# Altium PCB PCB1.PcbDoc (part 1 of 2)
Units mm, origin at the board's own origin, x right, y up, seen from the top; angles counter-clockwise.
Board outline 82.55 x 101.6 mm, 4 copper layers (Top Layer, GND, POWER, Bottom Layer), stack 1.586 mm thick; 125 components, 82 nets, 451 pads, 255 vias.
Unrouted connection lines stored in the file: 4.
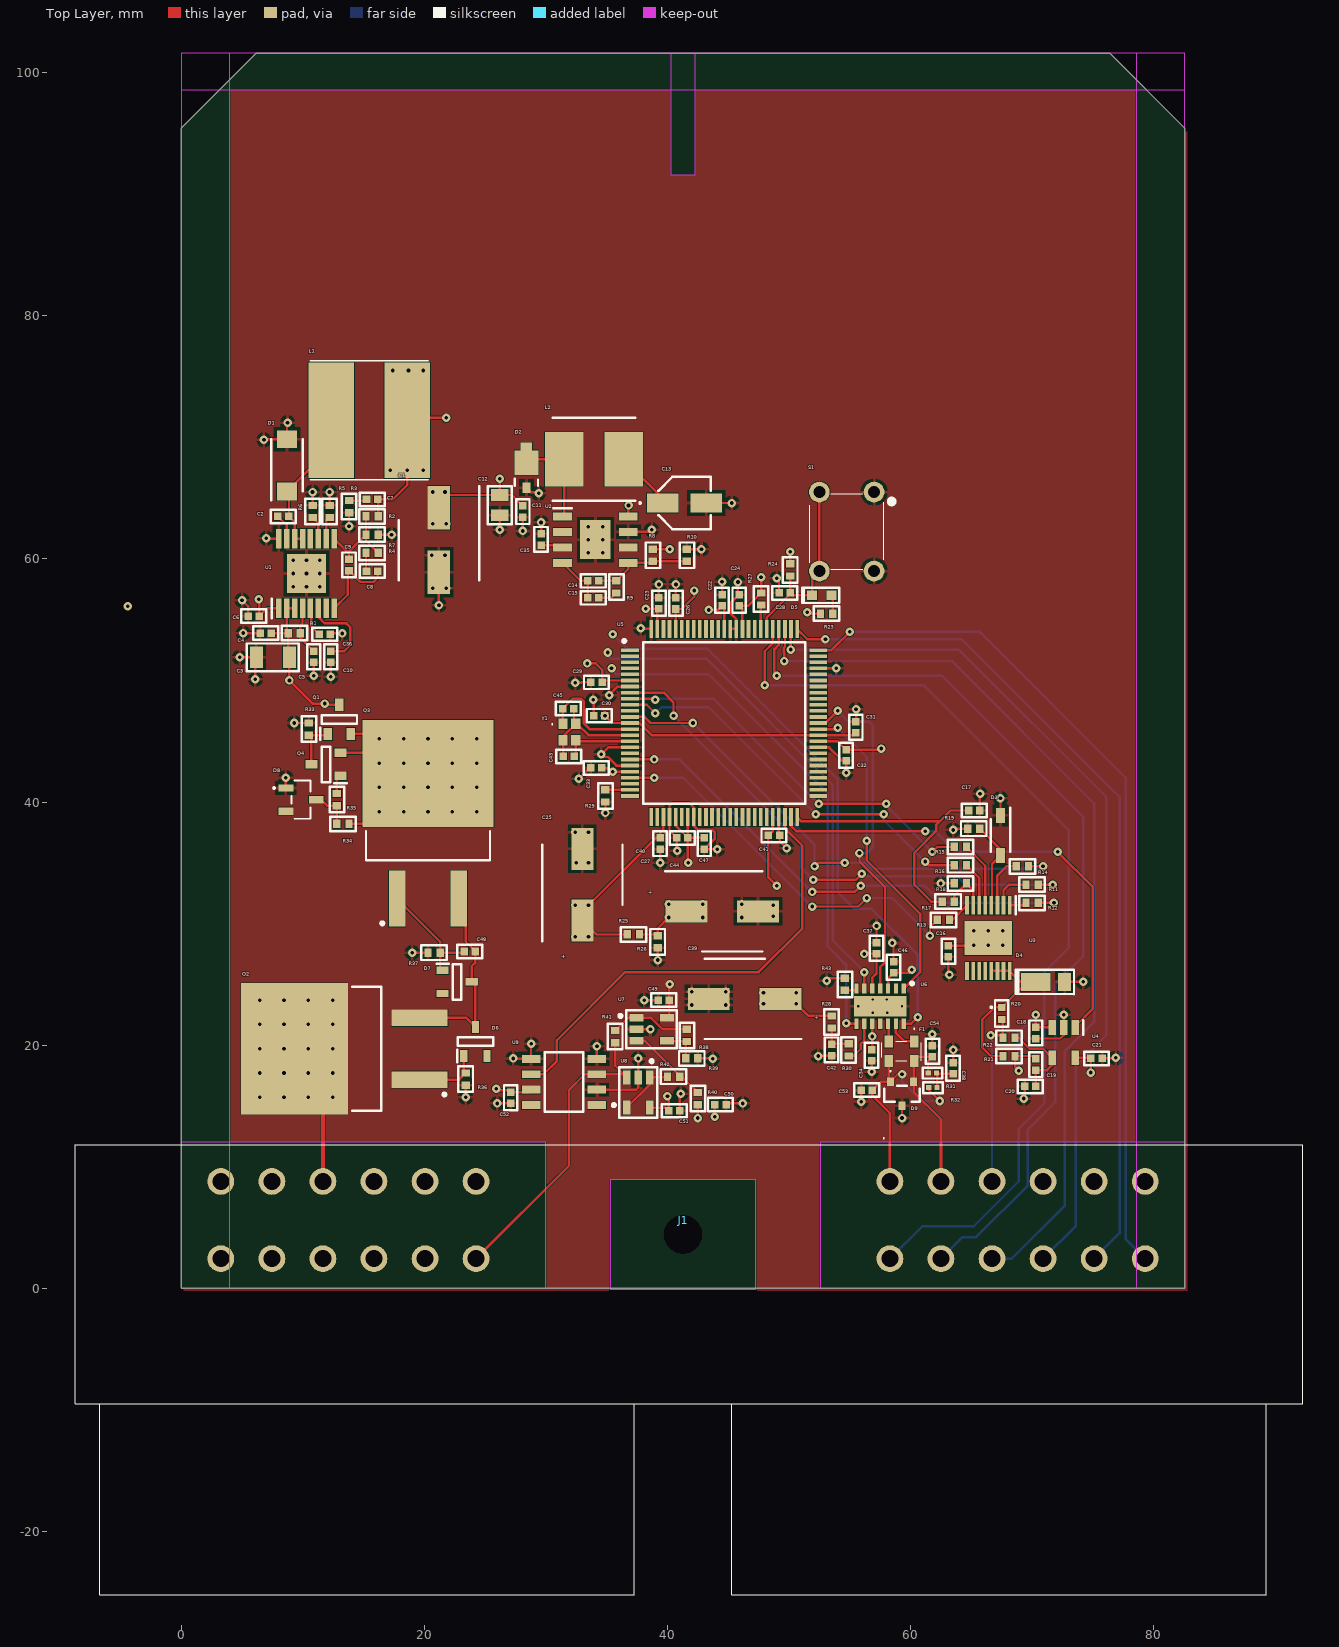
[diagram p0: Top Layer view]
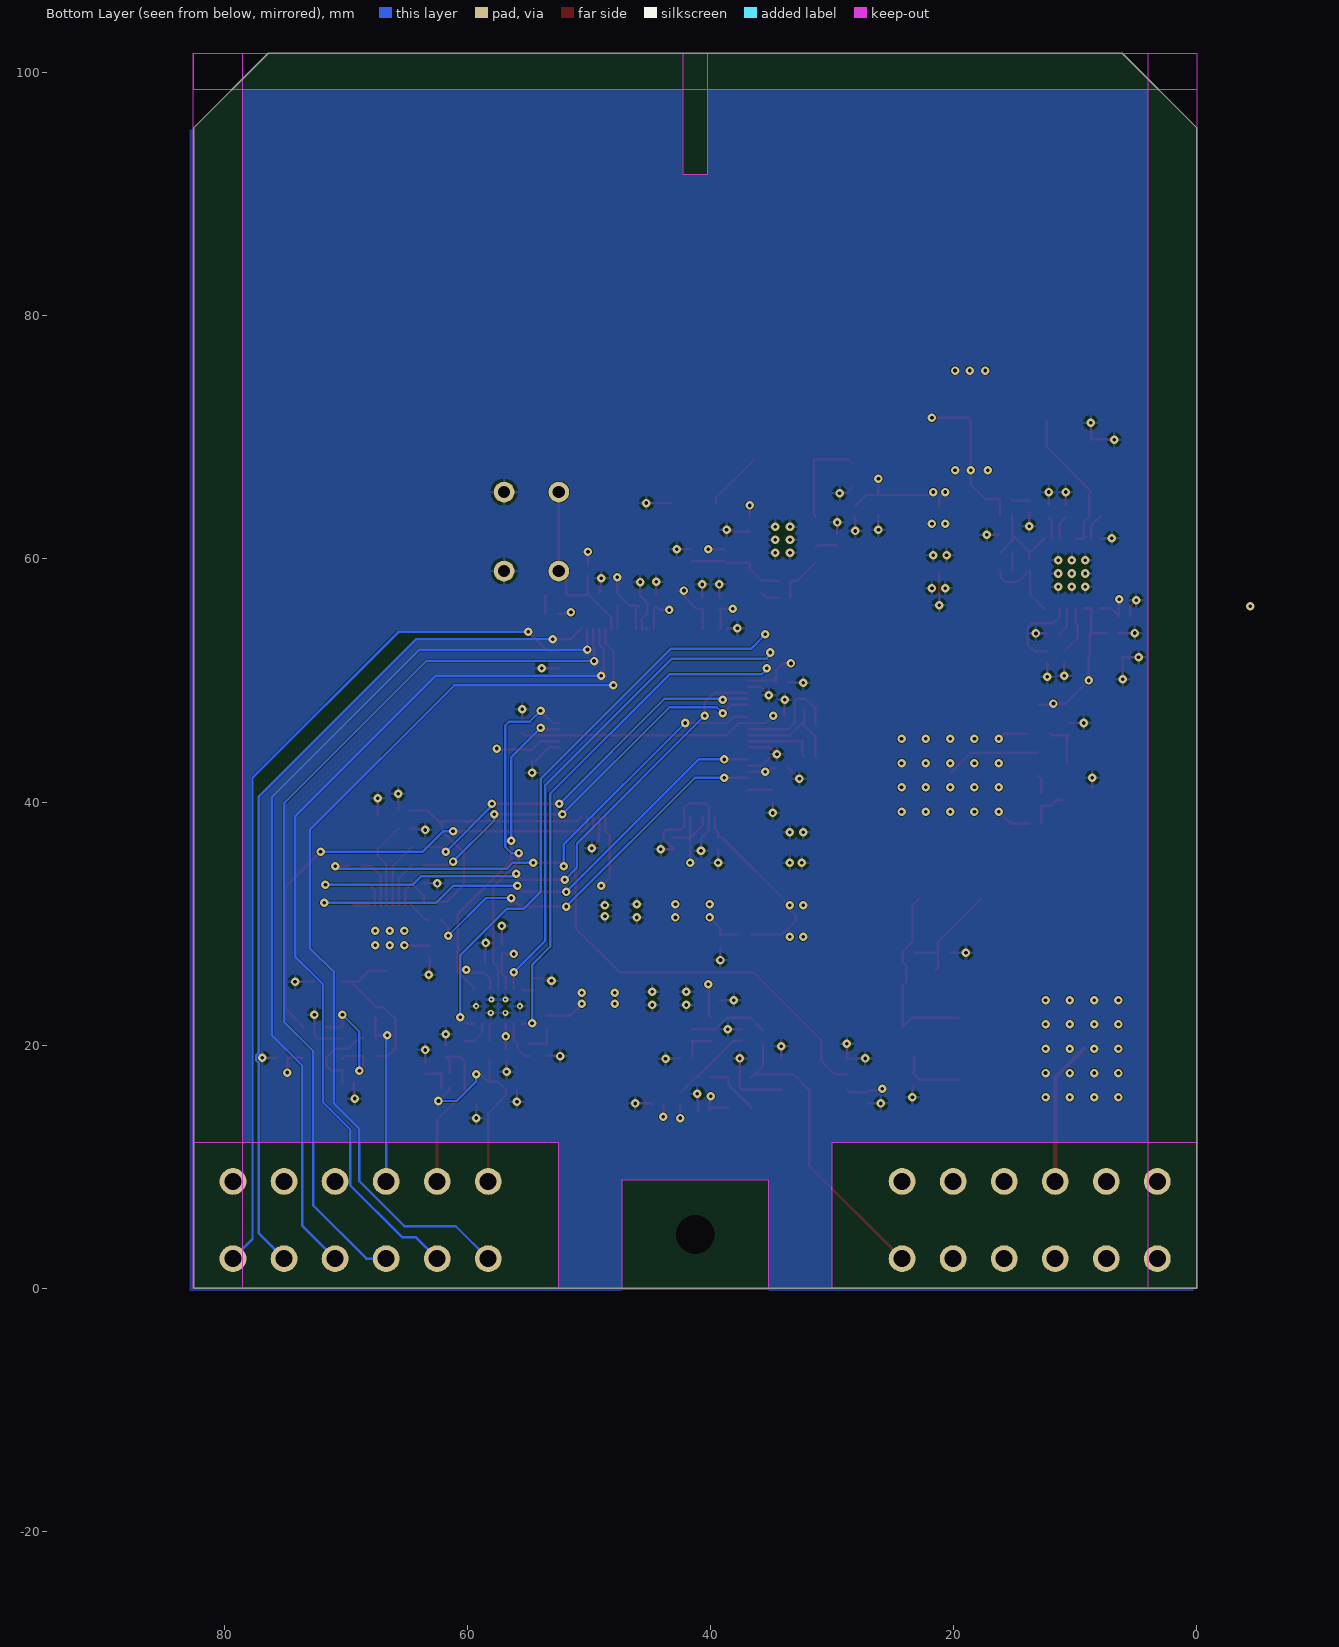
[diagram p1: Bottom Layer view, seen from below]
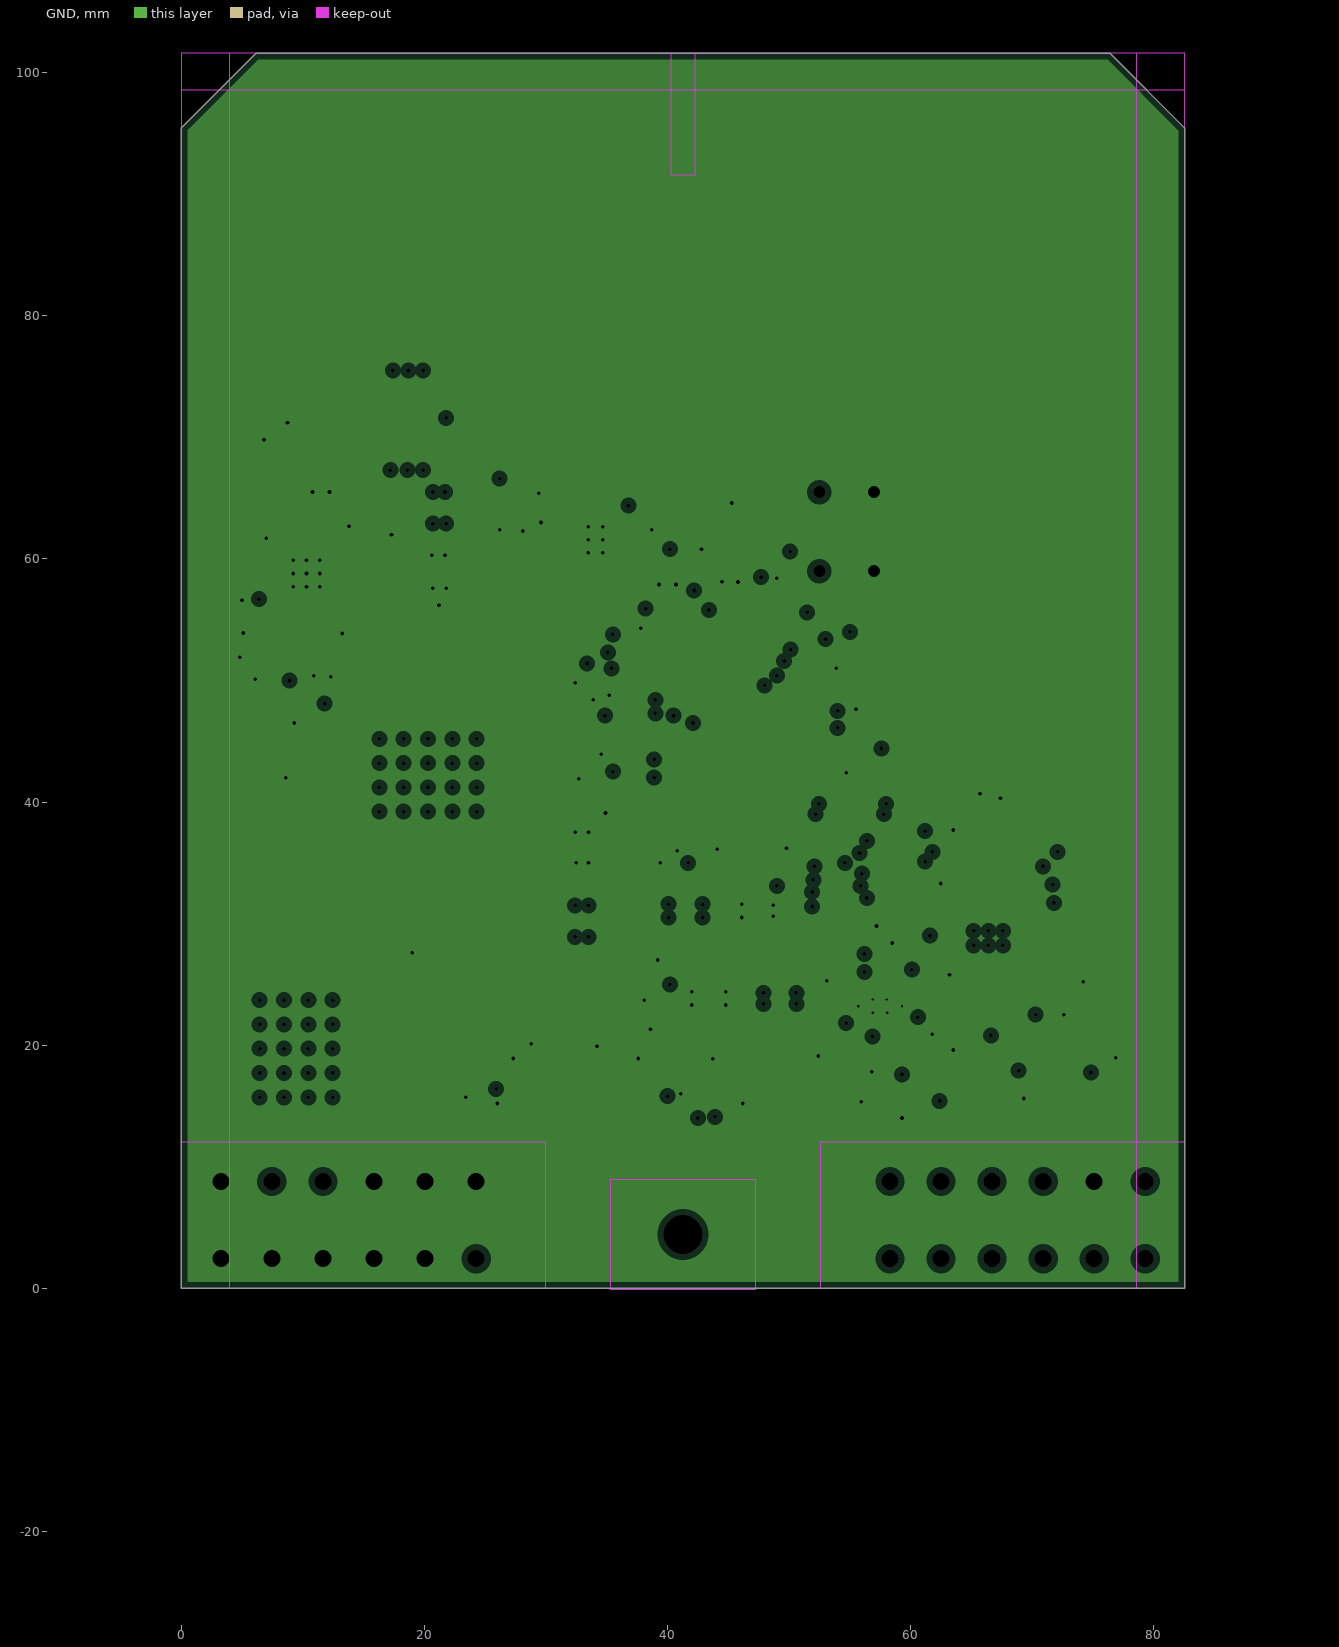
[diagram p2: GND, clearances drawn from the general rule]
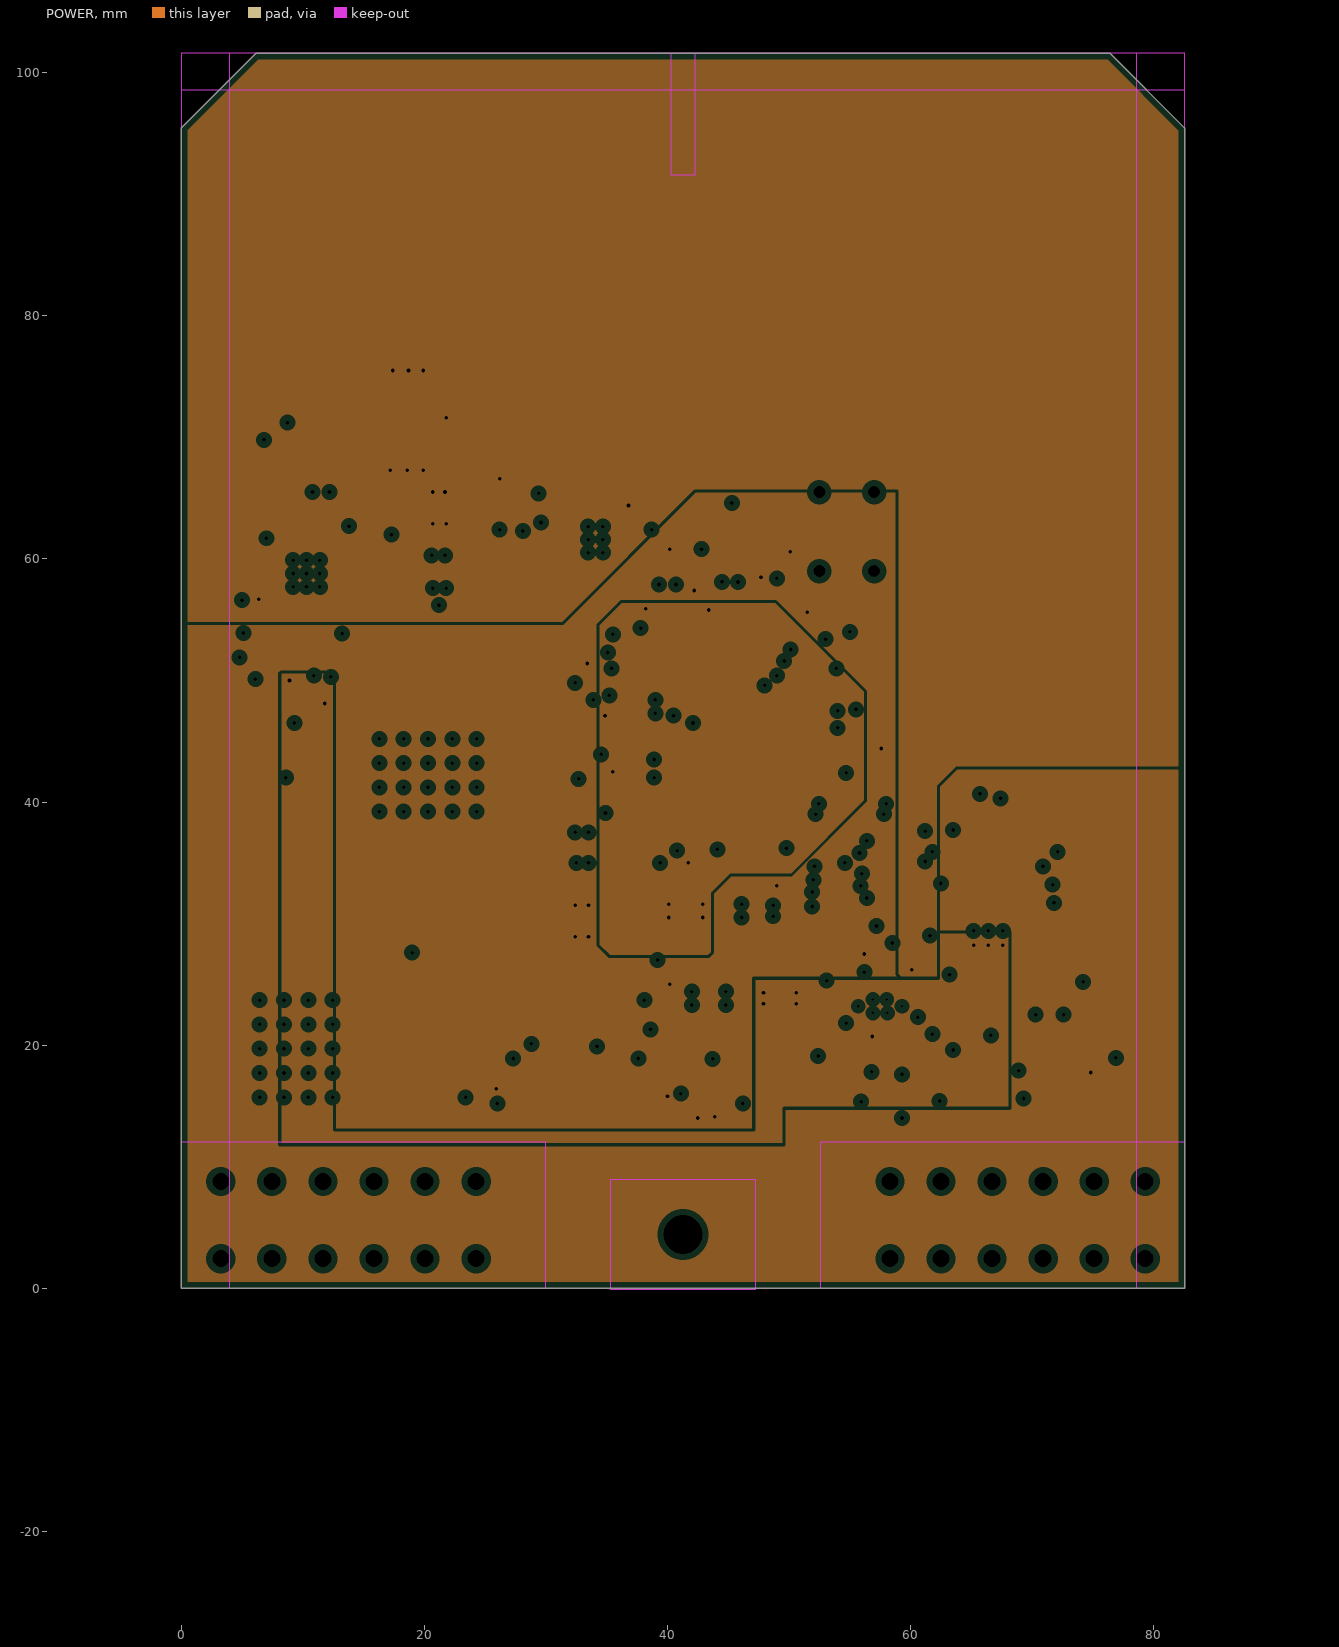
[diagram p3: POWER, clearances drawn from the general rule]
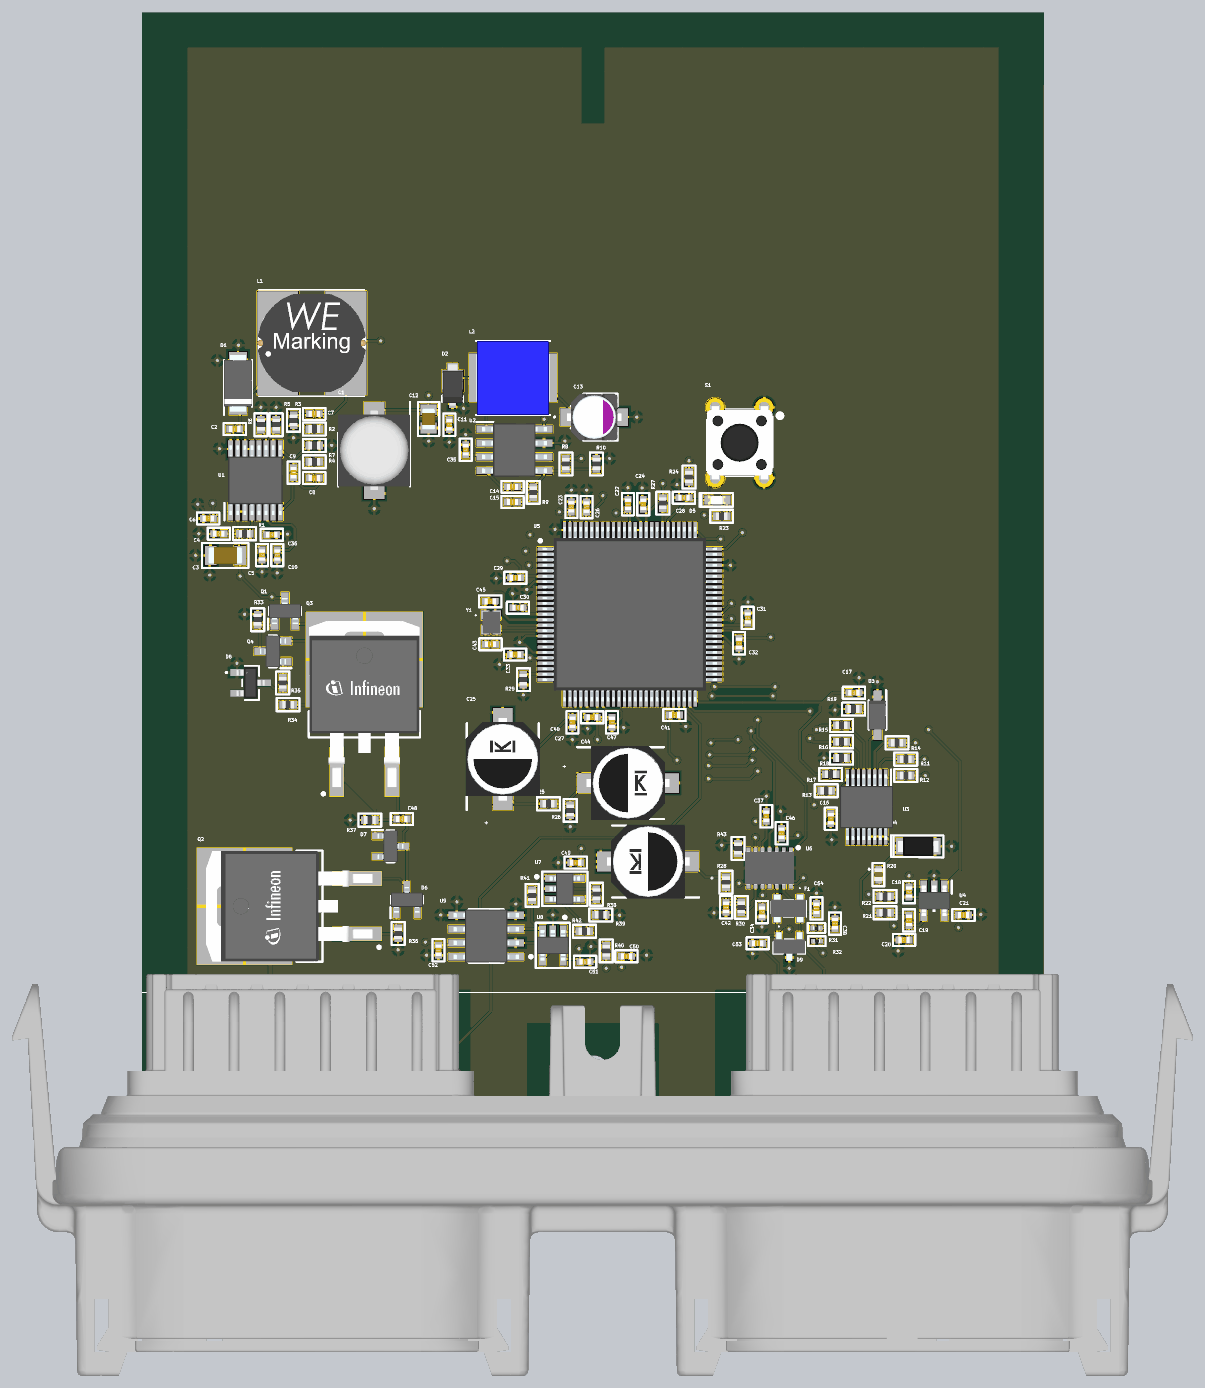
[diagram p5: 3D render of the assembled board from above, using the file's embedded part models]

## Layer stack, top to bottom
Top Solder: solder mask 0.0102, Solder Resist, Dk 3.5
Top Layer: signal copper 0.035
Dielectric 2: prepreg 0.2104, PP-006, Dk 4.1
GND: plane copper 0.0152, net GND
Dielectric 1: core 1.065, FR-4, Dk 4.8
POWER: plane copper 0.0152, net (Multiple Nets)
Dielectric 3: prepreg 0.2104, PP-006, Dk 4.1
Bottom Layer: signal copper 0.035
Bottom Solder: solder mask 0.0102, Solder Resist, Dk 3.5

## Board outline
0,0 0,95.456 6.144,101.6 76.406,101.6 82.55,95.456 82.55,0

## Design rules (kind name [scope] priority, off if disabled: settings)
Clearance [All] p1: gap=0.05 ignorepadtopadclearanceinfootprint=FALSE
DiffPairsRouting [All] p1: maxlimit=3 minlimit=0.07 mostfreqgap=1 toplayer_minwidth=0.2 toplayer_maxwidth=0.25 toplayer_prefwidth=0.25 bottomlayer_minwidth=0.2 bottomlayer_maxwidth=0.25 bottomlayer_prefwidth=0.25 maxuncoupledlength=12.7
HoleToHoleClearance [All] p1: gap=0.05 allowstackedmicrovias=TRUE
MinimumSolderMaskSliver [All] p1: minsoldermaskwidth=0.05
PlaneClearance [All] p1: clearance=0.508
PlaneConnect [All] p1: planeconnectstyle=Relief reliefexpansion=0.508 reliefentries=4 reliefconductorwidth=0.254 reliefairgap=0.254
PolygonConnect [All] p1: connectstyle=Relief reliefconductorwidth=0.254 reliefentries=4 polygonreliefangle="90 Angle" airgapwidth=0.254
RoutingVias [All] p1: holewidth=0.3 width=0.7 viastyle="Through Hole" minholewidth=0.3 minwidth=0.7 maxholewidth=0.3 maxwidth=0.7
SilkToSilkClearance [All] p1: silktosilkclearance=0.05
SilkToSolderMaskClearance [IsPad] p1: minsilkscreentomaskgap=0.05 clearancetoexposedcopper=TRUE
SolderMaskExpansion [All] p1: expansion=0.102 istentingtop=FALSE
SupplyNets "Schematic Supply Nets_5" [InNet('VBAT')] p1: voltage=0.000
SupplyNets "Schematic Supply Nets_4" [InNet('3V3')] p2: voltage=0.000
SupplyNets "Schematic Supply Nets_3" [InNet('1V2')] p3: voltage=0.000
SupplyNets "Schematic Supply Nets_2" [InNet('12V')] p4: voltage=0.000
SupplyNets "Schematic Supply Nets_1" [InNet('5V')] p5: voltage=0.000
SupplyNets "Schematic Supply Nets" [InNet('GND')] p6: voltage=0.000
Width [All] p1: maxlimit=0.35 minlimit=0.2 preferedwidth=0.2
23 further rules are at their usual default settings.

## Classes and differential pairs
component class NTC: C49 C50 C51 C52 R38 R39 R40 R41 R42 U7 U8 U9
component class Shunt: C18 C19 C20 C21 C34 C37 C38 C39 C42 C46 C53 C54 D9 F1 R20 R21 R22 R28 R30 R31 R32 R43 U4 U6
component class "Pump Driver": C16 C17 D3 D4 R11 R12 R13 R14 R15 R16 R17 R18 R19 U3
component class "Power Supply": C1 C2 C3 C4 C5 C6 C7 C8 C9 C10 C11 C12 C13 C14 C15 C35 C36 D1 D2 L1 L2 R1 R2 R3 R4 R5 R6 R7 R8 R9 R10 U1 U2
component class Microcontroller: C22 C23 C24 C25 C26 C27 C28 C29 C30 C31 C32 C33 C40 C41 C43 C44 C45 C47 D5 R23 R24 R25 R26 R27 R29 S1 U5 Y1
component class "Input Stage": C48 D6 D7 D8 J1 Q1 Q2 Q3 Q4 R33 R34 R35 R36 R37
differential pair CAN: +CAN_P -CAN_N

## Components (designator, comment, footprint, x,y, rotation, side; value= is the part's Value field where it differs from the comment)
C1 "15uF" CAPAE660X850N 21.2,61.55 r270 top
C2 "100nF" C0402 8.4,63.5 r0 top
C3 "4.7uF" CAPC3216X180N 7.54,51.9 r0 top
C4 "1uF" C0402 6.94,53.9 r0 top
C5 "1uF" C0402 10.9,51.94 r90 top
C6 "1uF" C0402 5.96,55.3 r180 top
C7 "680pF" C0402 15.7,64.9 r0 top
C8 "27nF" C0402 15.7,59 r180 top
C9 "220pF" C0402 13.8,59.5 r270 top
C10 "33nF" C0402 12.3,51.94 r90 top
C11 "220nF" C0402 28.1,63.9 r270 top
C12 "10uF" CAPC2012X145N 26.2,64.43 r90 top
C13 "33uF" 10SVPS10M 41.4,64.6 r0 top
C14 "270pF" C0402 33.9,58.2 r0 top
C15 "100nF" C0402 33.9,56.8 r0 top
C16 "100nF" C0402 63.119,27.73 r90 top
C17 "10nF" C0402 65.24,39.3 r180 top
C18 "1nF" C0402 70.3,21 r90 top
C19 "10nF" C0402 70.3,18.4 r270 top
C20 "1nF" C0402 69.84,16.6 r180 top
C21 "1uF" C0402 75.3,18.9 r180 top
C22 "100nF" C0402 44.5,56.6 r270 top
C23 "100nF" C0402 39.3,56.36 r270 top
C24 "100nF" C0402 45.9,56.6 r270 top
C25 "10uF" CAPAE660X565N 33,33.2 r90 top
C26 "100nF" C0402 40.7,56.34 r270 top
C27 "10uF" CAPAE660X565N 44.5,31 r0 top
C28 "100nF" C0402 49.64,57.2 r0 top
C29 "100nF" C0402 34.16,49.846 r0 top
C30 "100nF" C0402 34.4,47.1 r0 top
C31 "100nF" C0402 55.5,46.16 r270 top
C32 "100nF" C0402 54.7,43.84 r90 top
C33 "100nF" C0402 34.14,42.8 r0 top
C34 "100nF" C0402 56.8,19.16 r90 top
C35 "220nF" C0402 29.6,61.6 r90 top
C36 "1uF" C0402 11.8,53.8 r180 top
C37 "100nF" C0402 57.2,27.96 r270 top
C38 "4.7nF" C0402 63.5,18.1 r90 top
C39 "10uF" CAPAE660X565N 46.35,23.8 r180 top
C40 "100nF" C0402 39.395,36.585 r90 top
C41 "100nF" C0402 48.765,37.248 r180 top
C42 "22nF" C0402 53.5,19.6 r90 top
C43 "20pF" C0402 31.877,43.75 r0 top
C44 "100nF" C0402 41.221,37.045 r0 top
C45 "20pF" C0402 31.849,47.687 r180 top
C46 "100nF" C0402 58.6,26.4 r270 top
C47 "100nF" C0402 43.028,36.585 r90 top
C48 "1uF" C0402 23.74,27.7 r0 top
C49 "100nF" C0402 39.7,23.7 r0 top
C50 "100nF" C0402 44.36,15.1 r180 top
C51 "100nF" C0402 40.56,14.6 r180 top
C52 "100nF" C0402 27.1,15.66 r90 top
C53 "100pF" C0402 56.4,16.3 r180 top
C54 "100pF" C0402 61.8,19.5 r270 top
D1 "STPS2L25AFN" SODFL5226X110N 8.7,67.7 r90 top
D2 "STPS120MF" STPS120MF 28.4,67.5 r90 top
D3 "1N5819" SOD3716X125N 67.4,37.25 r270 top
D4 "DFLS1100-7" DFLS110 71.15,25.2 r0 top
D5 "150060AS75000" LED-0603 52.7,57 r0 top
D6 "BZX84C12" SOT96P237X111-3N 24.2,20.3 r90 top
D7 "BZX84C12" SOT96P237X111-3N 22.7,25.2 r0 top
D8 "BZX84B24" TRANS_BZX84_ROM-M 9.855,40.2 r270 top
D9 "PESD" PESD2CANFD36LTQR 59.3,16 r0 top
F1 "DLP31SN121ML2L" DLP31SN121ML2B 60.3,18.7 r270 top
J1 "ATM13-12PA-12PB-BM03" ATM1312PA12PBBM03 24.255,2.43 r0 top locked
L1 "12uH" WE-PD2_105455 15.475,71.4 r0 top
L2 "15uH" INDPM6868X420N 33.95,68.2 r0 top
Q1 "MMBT5401" SOT95P240X120-3N 13,46.8 r90 top
Q2 "IRF5210" TO254P1528X508-4_3N-V1 14.455,19.7 r180 top
Q3 "IRF5210" TO254P1528X508-4_3N-V1 20.3,37.2 r90 top
Q4 "MMBT5401" SOT95P240X120-3N 11.9,43.1 r180 top
R1 "0" R0402 9.3,53.9 r180 top
R2 "43k" R0402 15.7,63.5 r0 top value=43kR
R3 "1.3k" R0402 13.8,64.3 r90 top value=1.3kR
R4 "2.7k" R0402 15.7,60.5 r0 top value=2.7kR
R5 "51.1k" R0402 12.2,63.9 r270 top value=51.1kR
R6 "30k" R0402 10.8,63.9 r270 top value=30kR
R7 "8.2k" R0402 15.7,62 r180 top
R8 "4.7k" R0402 38.8,60.3 r90 top value=4.7kR
R9 "3.3k" R0402 35.8,57.7 r90 top value=3.3kR
R10 "1.05k" R0402 41.6,60.3 r270 top value=1.05kR
R11 "15k" R0402 70,33.2 r180 top
R12 "15k" R0402 70,31.7 r180 top
R13 "15k" R0402 62.7,30.3 r0 top
R14 "15k" R0402 69.2,34.7 r180 top
R15 "15k" R0402 64.1,36.3 r0 top
R16 "15k" R0402 64.1,34.8 r0 top
R17 "15k" R0402 63.1,31.8 r0 top
R18 "1k" R0402 64.1,33.3 r0 top
R19 "4.7k" R0402 65.2,37.8 r0 top value=4.7kR
R20 "10m" CSS0402FT10L0 67.5,22.6 r270 top
R21 "100R" R0402 68.1,19.1 r180 top
R22 "100R" R0402 68.1,20.6 r180 top
R23 "120R" R0402 53.1,55.5 r180 top
R24 "10k" R0402 50.1,59.1 r90 top
R25 "30k" R0402 37.2,29.1 r180 top value=30kR
R26 "17k2" R0402 39.2,28.5 r90 top value=17.2kR
R27 "10k" R0402 47.7,56.7 r90 top
R28 "3.3k" R0402 53.5,21.9 r90 top value=3.3kR
R29 "1k" R0402 34.9,40.5 r90 top
R30 "33k" R0402 54.9,19.6 r90 top
R31 "60R" R0201 61.8,17.7 r180 top
R32 "60R" R0201 61.84,16.5 r0 top
R33 "6k2" R0402 10.5,46 r90 top value=6.2kR
R34 "2k" R0402 13.3,38.2 r0 top
R35 "1k" R0402 12.8,40.2 r90 top
R36 "10R" R0402 23.4,17.2 r90 top
R37 "10R" R0402 20.8,27.6 r0 top
R38 "10k" R0402 41.6,20.8 r270 top
R39 "10k" R0402 42,18.9 r0 top
R40 "10k" R0402 42.5,15.6 r270 top
R41 "33k" R0402 35.7,20.7 r90 top
R42 "10k" R0402 40.5,17.4 r0 top
R43 "10k" R0402 54.6,25 r270 top
S1 "Pushbutton" Pushbutton 54.75,62.25 r270 top
U1 "A7987" SOP65P640X120-17N 10.3,58.8 r90 top
U2 "A7985A" SOIC127P600X170-9N 34.077,61.585 r0 top
U3 "VND7020AJ" SOP50P600X170-17N 66.4,28.8 r270 top
U4 "INA193" SOT95P280X145-5N 72.6,20.2 r270 top
U5 "TMS570" QFP50P1600X1600X160-100N 44.67,46.499 r0 top locked
U6 "TCAN1043" SON65P300X450X90-15N 57.5,23.2 r270 top
U7 "AD8538AUJZ" SOT95P280X100-5N 38.7,21.3 r0 top
U8 "AD8538AUJZ" SOT95P280X100-5N 37.6,16.1 r270 top
U9 "MAX4194" SOIC127P600X175-8N 31.488,16.965 r180 top
Y1 "16MHz" ECS1601037B2CTNTR 31.928,45.757 r270 top

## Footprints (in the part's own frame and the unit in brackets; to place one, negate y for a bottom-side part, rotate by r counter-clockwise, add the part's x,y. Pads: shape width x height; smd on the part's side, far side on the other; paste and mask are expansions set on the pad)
10SVPS10M [mm]
  rect 2.6x1.6 smd: 1(-1.8,0) 2(1.8,0)
  silkscreen extent -3.7,-2.15 2.15,2.15, body extent -2.5,-2.15 2.5,2.15, height 5.43
ATM1312PA12PBBM03 [mm]
  round 2.2 hole 1.4: A1(0,0) A2(-4.2,0) A3(-8.4,0) A4(-12.6,0) A5(-16.8,0) A6(-21,0) A7(-21,6.35) A8(-16.8,6.35) A9(-12.6,6.35) A10(-8.4,6.35) A11(-4.2,6.35) A12(0,6.35) B1(34.05,6.35) B2(38.25,6.35) B3(42.45,6.35) B4(46.65,6.35) B5(50.85,6.35) B6(55.05,6.35) B7(55.05,0) B8(50.85,0) B9(46.65,0) B10(42.45,0) B11(38.25,0) B12(34.05,0)
  round 1.6 hole 3.2 unplated: MH1(17.02,1.98)
  silkscreen extent -32.97,-27.65 68.02,9.95, body extent -36.24,-25.85 72.06,11.05, height 25.1
C0402 [mm]
  rect 0.62x0.62 smd: 1(-0.46,0) 2(0.46,0)
  silkscreen extent -1.02,-0.55 1.02,0.55, body extent -0.53,-0.28 0.53,0.27, height 0.55
CAPAE660X565N [mm]
  rect 3.45x1.8 smd: 1(-2.95,0) 2(2.95,0)
  silkscreen extent -4.67,-3.3 3.3,3.3, body extent -3.8,-3.4 3.8,3.4, height 5.66
CAPAE660X850N [mm]
  rect 3.6x1.85 smd: 1(-2.65,0) 2(2.65,0)
  silkscreen extent -4.45,-3.3 3.3,3.3, body extent -3.65,-3.3 3.65,3.3, height 8
CAPC2012X145N [mm]
  rect 0.97x1.47 smd: 1(-0.83,0) 2(0.83,0)
  silkscreen extent -1.58,-0.97 1.55,0.97, body extent -1,-0.63 1,0.63, height 1.45
CAPC3216X180N [mm]
  rect 1.07x1.78 smd: 1(-1.36,0) 2(1.36,0)
  silkscreen extent -2.16,-1.14 2.12,1.14, body extent -1.6,-0.8 1.6,0.8, height 1.8
CSS0402FT10L0 [mm]
  rect 0.6x0.6 smd: 1(-0.5,0) 2(0.5,0)
  silkscreen extent -1.07,-0.9 1.07,0.53, body extent -0.57,-0.36 0.57,0.36, height 0.41
DFLS110 [mm]
  rect 2.4x1.5 smd: 1(-0.85,0)
  rect 1.05x1.5 smd: 2(1.525,0)
  silkscreen extent -2.5,-1.02 2.3,1, body extent -1.85,-0.9 1.85,0.88, height 0.98
DLP31SN121ML2B [mm]
  rect 1x0.7 smd: 1(-1.6,0) 2(0,0) 3(0,-2.1) 4(-1.6,-2.1)
  silkscreen extent -2.7,-2.65 0,0.6, body extent -2.03,-2.65 0.43,0.55, height 1.4
ECS1601037B2CTNTR [mm]
  rect 0.85x0.75 smd: 1(-0.675,-0.525) 2(0.675,-0.525) 3(0.675,0.525) 4(-0.675,0.525)
  silkscreen extent -0.7,-1.45 -0.6,-1.35, body extent -1.02,-0.82 1.02,0.82, height 0.6
INDPM6868X420N [mm]
  rect 3.15x4.45 smd: 1(-2.45,0) 2(2.45,0)
  silkscreen extent -3.4,-3.4 3.4,3.4, body extent -3.4,-3.4 3.4,3.4, height 4.2
LED-0603 [mm]
  rect 0.8x0.8 smd: 1(-0.8,0) 2(0.8,0)
  silkscreen extent -1.63,-0.63 1.43,0.63, body extent -0.85,-0.43 0.75,0.37, height 0.81
PESD2CANFD36LTQR [mm]
  rect 0.6x0.7 smd: 1(-0.95,1) 2(0.95,1) 3(0,-1)
  silkscreen extent -1.45,-0.65 1.45,1.9, body extent -1.45,-1.29 1.45,1.29, height 1.2
Pushbutton [mm]
  round 1.7 hole 1: 1(-3.25,2.25) 2(3.25,2.25) 3(-3.25,-2.25) 4(3.25,-2.25)
  silkscreen extent -3.1,-3.05 3.1,3.9, body extent -3.9,-3 3.9,3, height 7
QFP50P1600X1600X160-100N [mm]
  rect 1.475x0.3 smd: 1(-7.738,6) 2(-7.738,5.5) 3(-7.738,5) 4(-7.738,4.5) 5(-7.738,4) 6(-7.738,3.5) 7(-7.738,3) 8(-7.738,2.5) 9(-7.738,2) 10(-7.738,1.5) 11(-7.738,1) 12(-7.738,0.5) 13(-7.738,0) 14(-7.738,-0.5) 15(-7.738,-1) 16(-7.738,-1.5) 17(-7.738,-2) 18(-7.738,-2.5) 19(-7.738,-3) 20(-7.738,-3.5) 21(-7.738,-4) 22(-7.738,-4.5) 23(-7.738,-5) 24(-7.738,-5.5) 25(-7.738,-6) 51(7.738,-6) 52(7.738,-5.5) 53(7.738,-5) 54(7.738,-4.5) 55(7.738,-4) 56(7.738,-3.5) 57(7.738,-3) 58(7.738,-2.5) 59(7.738,-2) 60(7.738,-1.5) 61(7.738,-1) 62(7.738,-0.5) 63(7.738,0) 64(7.738,0.5) 65(7.738,1) 66(7.738,1.5) 67(7.738,2) 68(7.738,2.5) 69(7.738,3) 70(7.738,3.5) 71(7.738,4) 72(7.738,4.5) 73(7.738,5) 74(7.738,5.5) 75(7.738,6)
  rect 0.3x1.475 smd: 26(-6,-7.738) 27(-5.5,-7.738) 28(-5,-7.738) 29(-4.5,-7.738) 30(-4,-7.738) 31(-3.5,-7.738) 32(-3,-7.738) 33(-2.5,-7.738) 34(-2,-7.738) 35(-1.5,-7.738) 36(-1,-7.738) 37(-0.5,-7.738) 38(0,-7.738) 39(0.5,-7.738) 40(1,-7.738) 41(1.5,-7.738) 42(2,-7.738) 43(2.5,-7.738) 44(3,-7.738) 45(3.5,-7.738) 46(4,-7.738) 47(4.5,-7.738) 48(5,-7.738) 49(5.5,-7.738) 50(6,-7.738) 76(6,7.738) 77(5.5,7.738) 78(5,7.738) 79(4.5,7.738) 80(4,7.738) 81(3.5,7.738) 82(3,7.738) 83(2.5,7.738) 84(2,7.738) 85(1.5,7.738) 86(1,7.738) 87(0.5,7.738) 88(0,7.738) 89(-0.5,7.738) 90(-1,7.738) 91(-1.5,7.738) 92(-2,7.738) 93(-2.5,7.738) 94(-3,7.738) 95(-3.5,7.738) 96(-4,7.738) 97(-4.5,7.738) 98(-5,7.738) 99(-5.5,7.738) 100(-6,7.738)
  silkscreen extent -8.35,-6.65 6.65,6.87, body extent -8,-8 8,8, height 1.6
R0201 [mm]
  rect 0.44x0.42 smd: 1(-0.34,0) 2(0.34,0)
  silkscreen extent -0.8,-0.45 0.8,0.45, body extent -0.3,-0.15 0.3,0.15, height 0.26
R0402 [mm]
  rect 0.6x0.7 smd: 1(-0.5,0) 2(0.5,0)
  silkscreen extent -1.05,-0.6 1.05,0.6, body extent -0.53,-0.35 0.53,0.36, height 0.51
SOD3716X125N [mm]
  rect 1.25x0.75 smd: 1(-1.65,0) 2(1.65,0)
  silkscreen extent -2.27,-0.8 1.35,0.8, body extent -1.35,-0.8 1.35,0.8, height 1.25
SODFL5226X110N [mm]
  rect 1.46x1.67 smd: 1(-2.15,0) 2(2.15,0)
  silkscreen extent -2.88,-1.29 2.14,1.29, body extent -2.59,-1.29 2.59,1.29, height 1.1
SOIC127P600X170-9N [mm]
  rect 1.525x0.65 smd: 1(-2.712,1.905) 2(-2.712,0.635) 3(-2.712,-0.635) 4(-2.712,-1.905) 5(2.712,-1.905) 6(2.712,-0.635) 7(2.712,0.635) 8(2.712,1.905)
  rect 2.51x3.2 smd paste-4: 9(0,0)
  silkscreen extent -3.47,2.58 -1.95,2.58, body extent -3,-2.45 3,2.45, height 1.7
SOIC127P600X175-8N [mm]
  rect 1.525x0.65 smd: 1(-2.712,1.905) 2(-2.712,0.635) 3(-2.712,-0.635) 4(-2.712,-1.905) 5(2.712,-1.905) 6(2.712,-0.635) 7(2.712,0.635) 8(2.712,1.905)
  silkscreen extent -4.23,-2.45 1.6,2.45, body extent -3,-2.45 3,2.45, height 1.75
SON65P300X450X90-15N [mm]
  rect 0.85x0.35 smd: 1(-1.45,1.95) 2(-1.45,1.3) 3(-1.45,0.65) 4(-1.45,0) 5(-1.45,-0.65) 6(-1.45,-1.3) 7(-1.45,-1.95) 8(1.45,-1.95) 9(1.45,-1.3) 10(1.45,-0.65) 11(1.45,0) 12(1.45,0.65) 13(1.45,1.3) 14(1.45,1.95)
  rect 1.7x4.3 smd paste-5: 15(0,0)
  silkscreen extent -2,2.5 -1.75,2.75, body extent -1.55,-2.25 1.55,2.25, height 0.9
SOP50P600X170-17N [mm]
  rect 1.5x0.3 smd: 1(-2.7,1.75) 2(-2.7,1.25) 3(-2.7,0.75) 4(-2.7,0.25) 5(-2.7,-0.25) 6(-2.7,-0.75) 7(-2.7,-1.25) 8(-2.7,-1.75) 9(2.7,-1.75) 10(2.7,-1.25) 11(2.7,-0.75) 12(2.7,-0.25) 13(2.7,0.25) 14(2.7,0.75) 15(2.7,1.25) 16(2.7,1.75)
  rect 2.8x3.91 smd paste-4: 17(0,0)
  silkscreen extent -3.45,2.25 -1.95,2.25, body extent -3,-2.45 3,2.45, height 1.7
SOP65P640X120-17N [mm]
  rect 1.6x0.45 smd: 1(-2.875,2.275) 2(-2.875,1.625) 3(-2.875,0.975) 4(-2.875,0.325) 5(-2.875,-0.325) 6(-2.875,-0.975) 7(-2.875,-1.625) 8(-2.875,-2.275) 9(2.875,-2.275) 10(2.875,-1.625) 11(2.875,-0.975) 12(2.875,-0.325) 13(2.875,0.325) 14(2.875,0.975) 15(2.875,1.625) 16(2.875,2.275)
  rect 3.2x3.2 smd paste-3: 17(0,0)
  silkscreen extent -3.67,2.85 -2.07,2.85, body extent -3.2,-2.5 3.2,2.5, height 1.2
SOT95P240X120-3N [mm]
  rect 1x0.7 smd: 1(-1.2,0.95) 2(-1.2,-0.95) 3(1.2,0)
  silkscreen extent -1.7,-1.46 0.35,1.55, body extent -1.2,-1.46 1.2,1.46, height 1.2
SOT95P280X100-5N [mm]
  rect 1.15x0.6 smd: 1(-1.25,0.95) 2(-1.25,0) 3(-1.25,-0.95) 4(1.25,-0.95) 5(1.25,0.95)
  silkscreen extent -2.7,-1.58 2.07,1.58, body extent -1.4,-1.45 1.4,1.45, height 1
SOT95P280X145-5N [mm]
  rect 1.2x0.6 smd: 1(-1.25,0.95) 2(-1.25,0) 3(-1.25,-0.95) 4(1.25,-0.95) 5(1.25,0.95)
  silkscreen extent -1.85,1.63 -0.65,1.63, body extent -1.4,-1.45 1.4,1.45, height 1.2
SOT96P237X111-3N [mm]
  rect 1x0.6 smd: 1(-1.2,0.955) 2(-1.2,-0.955) 3(1.2,0)
  silkscreen extent -1.7,-1.46 0.35,1.51, body extent -1.18,-1.46 1.18,1.46, height 1.11
STPS120MF [mm]
  rect 0.85x0.65 smd: 1(-1.64,0)
  rect 2x1.95 smd: 2(0.415,0)
  rect 0.65x0.95 smd: 3(1.74,0)
  silkscreen extent -1.5,-0.95 -0.9,0.95, body extent -1.86,-0.96 1.94,0.96, height 0.85
TO254P1528X508-4_3N-V1 [mm] "TO,2.54mm pitch;3 pin,15.28mm L X 9.00mm W X 5.08mm H body"
  rect 4.6x1.35 smd paste-0.05 mask+0: 1(-5.155,2.54) 3(-5.155,-2.54)
  rect 8.8x10.8 smd paste-4.4 mask+0: 2(5.155,0)
  silkscreen extent -7.31,-5.1 0.4,5.1, body extent -6.59,-5.08 8.69,5.08, height 5.09
TRANS_BZX84_ROM-M [mil]
  rect 24x48 smd paste+0 mask+0: 1(-37.4,-49) 2(37.4,-49) 3(0,49)
  silkscreen extent -62,-91 62,31, body extent -57,-51 57,51, height 45
WE-PD2_105455 [mm]
  rect 3.75x9.5 smd: 1(-3.125,0) 2(3.125,0)
  silkscreen extent -4.86,-4.89 4.84,4.89, body extent -5.04,-4.5 5.04,4.5, height 5.4

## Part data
C1: library part AHA0608150M050R, "Hybrid Aluminum V-Chip, 15uF, 50V", Manufacturer="Kyocera AVX", Supplier Part Number=581-AHA0608150M050R
C2 C15 C16 C22 C23 C24 C26 C28 C29 C30 C31 C32 C33 C34 C37 C40 C41 C44 C46 C47 C49 C50 C51 C52: library part C0402C104K3PACTU, "Ceramic Capacitor, Multilayer, Ceramic, 25V, 10% +Tol, 10% -Tol, X5R, 15% TC, 0.1uF, Surface Mount, 0402", Capacitor Type=Ceramic, Case/Package=0402, Manufacturer=KEMET, Max Operating Temperature=85°C, Min Operating Temperature=-55°C, Package Shape=Rectangular, Rated DC Voltage (URdc)=25V, Supplier Part Number=80-C0402C104K3P, Temperature Characteristics Code=X5R, Tolerance  (fill in as +-)=10%
C3: library part EMK316BJ475MLHT, "Ceramic Capacitor, Multilayer, Ceramic, 16V, 20% +Tol, 20% -Tol, X5R, 15% TC, 4.7uF, Surface Mount, 1206", Manufacturer="Taiyo Yuden", Supplier Part Number=963-EMK316BJ475MLHT
C4 C5 C6 C21 C36 C48: library part C0402C105K4PAC7411, "Ceramic Capacitor, Multilayer, Ceramic, 16V, 10% +Tol, 10% -Tol, X5R, 15% TC, 1uF, Surface Mount, 0402", Capacitor Type=Ceramic, Case/Package=0402, Manufacturer=KEMET, Max Operating Temperature=85°C, Min Operating Temperature=-55°C, Package Shape=Rectangular, Rated DC Voltage (URdc)=16V, Supplier Part Number=80-C0402C105K4P7411, Temperature Characteristics Code=X5R, Tolerance  (fill in as +-)=10%
C7: library part C0402C681K8RACTU, "Ceramic Capacitor, Multilayer, Ceramic, 10V, 10% +Tol, 10% -Tol, X7R, 15% TC, 0.00068uF, Surface Mount, 0402", Capacitor Type=Ceramic, Case/Package=0402, Manufacturer=KEMET, Max Operating Temperature=125°C, Min Operating Temperature=-55°C, Package Shape=Rectangular, Package Style=SMTMeter, Rated DC Voltage (URdc)=10V, Supplier Part Number=80-C0402C681K8RACTU, Temperature Characteristics Code=X7R, Tolerance  (fill in as +-)=10%
C8: library part C0402C273K4RALTU, ".027Uf 16.0V Rohs Compliant: No", Manufacturer=KEMET, Supplier Part Number=80-C0402C273K4RALTU
C9: library part C0402S221K5RACAUTO, "Ceramic Capacitor, Multilayer, Ceramic, 50V, 10% +Tol, 10% -Tol, X7R, 15% TC, 0.00022uF, Surface Mount, 0402", Capacitor Type=Ceramic, Manufacturer=KEMET, Supplier Part Number=80-C0402S221K5RAUTO
C10: library part C0402C333M4REC7411, "Ceramic Capacitor, Multilayer, Ceramic, 16V, 20% +Tol, 20% -Tol, X7R, 15% TC, 0.033uF, Surface Mount, 0402", Capacitor Type=Ceramic, Manufacturer=KEMET, Supplier Part Number=80-C0402C333M4RECLR
C11 C35: library part C0402C224K9PAC7411, "Ceramic Capacitor, Multilayer, Ceramic, 6.3V, 10% +Tol, 10% -Tol, X5R, 15% TC, 0.22uF, Surface Mount, 0402", Capacitor Type=Ceramic, Case/Package=0402, Manufacturer=KEMET, Max Operating Temperature=85°C, Min Operating Temperature=-55°C, Package Shape=Rectangular, Package Style=SMTMeter, Rated DC Voltage (URdc)=6.3V, Supplier Part Number=80-C0402C224K9PACLR, Temperature Characteristics Code=X5R, Tolerance  (fill in as +-)=10%
C12: library part GRM21BR60J106KE19L, "Ceramic Capacitor, Multilayer, Ceramic, 6.3V, 10% +Tol, 10% -Tol, X5R, 15% TC, 10uF, Surface Mount, 0805", Capacitor Type=Ceramic, Case/Package=0805, Manufacturer=Murata, Max Operating Temperature=85°C, Min Operating Temperature=-55°C, Package Shape=Rectangular, Package Style=SMTMeter, Rated DC Voltage (URdc)=6.3V, Temperature Characteristics Code=X5R, Tolerance  (fill in as +-)=10%
C13: library part 4SVP33M, "Aluminum Electrolytic Capacitor, Polarized, Aluminum (solid Polymer), 4V, 20% +Tol, 20% -Tol, 33uF, Surface Mount, 1717", Capacitor Type=Aluminium, Case/Package=1717, ESR (Equivalent Series Resistance)=200mR, Leakage Current=66uA, Manufacturer=Panasonic, Manufacturer Series=SVP, Max Operating Temperature=105°C, Min Operating Temperature=-55°C, Package Shape=Cylindrical, Package Style=SMTMeter, Rated DC Voltage (URdc)=4V, Ripple Current=37mA, Supplier Part Number=667-4SVP33M, Tolerance  (fill in as +-)=20%
C14: library part C0402C271J5GAC7411, "Ceramic Capacitor, Multilayer, Ceramic, 50V, 5% +Tol, 5% -Tol, C0G, 30ppm/Cel TC, 0.00027uF, Surface Mount, 0402", Capacitor Type=Ceramic, Case/Package=0402, Manufacturer=KEMET, Max Operating Temperature=125°C, Min Operating Temperature=-55°C, Package Shape=Rectangular, Package Style=SMTMeter, Rated DC Voltage (URdc)=50V, Supplier Part Number=80-C0402C271J5G7411, Temperature Characteristics Code=C0G, Tolerance  (fill in as +-)=5%
C17 C19: library part C0402T103K4RALTU, "Ceramic Capacitor, Multilayer, Ceramic, 16V, 10% +Tol, 10% -Tol, X7R, 15% TC, 0.01uF, Surface Mount, 0402", Capacitor Type=Ceramic, Case/Package=0402, Manufacturer=KEMET, Max Operating Temperature=125°C, Min Operating Temperature=-55°C, Package Shape=Rectangular, Package Style=SMTMeter, Rated DC Voltage (URdc)=16V, Supplier Part Number=80-C0402T103K4RALTU, Temperature Characteristics Code=X7R, Tolerance  (fill in as +-)=10%
C18 C20: library part C0402C102J5GACAUTO, "Ceramic Capacitor, Multilayer, Ceramic, 50V, 5% +Tol, 5% -Tol, C0G, 30ppm/Cel TC, 0.001uF, Surface Mount, 0402", Capacitor Type=Ceramic, Case/Package=0402, Manufacturer=KEMET, Max Operating Temperature=125°C, Min Operating Temperature=-55°C, Package Style=SMTMeter, Rated DC Voltage (URdc)=50V, Supplier Part Number=80-C0402C102J5GAUTO, Temperature Characteristics Code=C0G, Tolerance  (fill in as +-)=5%
C25 C27 C39: library part EXV106M050A9GAA, "Aluminum Electrolytic Capacitor, Polarized, Aluminum (wet), 50V, 20% +Tol, 20% -Tol, 10uF, Surface Mount, 2626", Capacitor Type=Aluminium, Case/Package=2626, ESR (Equivalent Series Resistance)=2.6R, Leakage Current=5uA, Manufacturer=KEMET, Max Operating Temperature=105°C, Min Operating Temperature=-55°C, Package Shape=Cylindrical, Package Style=SMTMeter, Rated DC Voltage (URdc)=50V, Ripple Current=98mA, Supplier Part Number=80-EXV106M050A9GAA, Tolerance  (fill in as +-)=20%
C38: library part C0402C472J4JACAUTO, "Cap Ceramic 0.0047uF 16V U2J 5% Pad SMD 0402 125C T/R", Manufacturer=KEMET, Supplier Part Number=80-C0402C472J4JAUTO
C42: library part C0402C223J5RACTU, "Ceramic Capacitor, Multilayer, Ceramic, 50V, 5% +Tol, 5% -Tol, X7R, 15% TC, 0.022uF, Surface Mount, 0402", Capacitor Type=Ceramic, Case/Package=0402, Manufacturer=KEMET, Max Operating Temperature=125°C, Min Operating Temperature=-55°C, Package Shape=Rectangular, Package Style=SMTMeter, Rated DC Voltage (URdc)=50V, Supplier Part Number=80-C0402C223J5RACTU, Temperature Characteristics Code=X7R, Tolerance  (fill in as +-)=5%
C43 C45: library part C0402C200F5GACTU, "Ceramic Capacitor, Multilayer, Ceramic, 50V, 1% +Tol, 1% -Tol, C0G, 30ppm/Cel TC, 0.00002uF, Surface Mount, 0402", Capacitor Type=Ceramic, Case/Package=0402, Manufacturer=KEMET, Max Operating Temperature=125°C, Min Operating Temperature=-55°C, Package Style=SMTMeter, Rated DC Voltage (URdc)=50V, Supplier Part Number=80-C0402C200F5GACTU, Temperature Characteristics Code=C0G, Tolerance  (fill in as +-)=1%
C53 C54: library part C0402C101K3RACAUTO, "Multilayer Ceramic Capacitors MLCC - SMD/SMT 25V 100pF X7R 0402 10% AEC-Q200", Manufacturer=KEMET, Supplier Part Number=80-C0402C101K3RAUTO
D1: "Rectifier Diode", Manufacturer=STMicroelectronics, Supplier Part Number=3387295
D2: "Rectifier Diode, Schottky, 1 Phase, 1 Element, 1A, 20V V(RRM), Silicon, DO-222AA", Case Connection=CATHODE, Forward Voltage=410mV, Manufacturer=STMicroelectronics, Max Operating Temperature=150°C, Max Output current=1A, Non-rep Pk Forward Current-Max=50A, Package Body Material=Plastic, Package Shape=Rectangular, Package Style="SMALL OUTLINEMeter", Rep Pk Reverse Voltage-Max=20V, Supplier Part Number=511-STPS120MF
D3: library part 1N5819HW-7-F, "Rectifier Diode, Schottky, 1 Phase, 1 Element, 1A, 40V V(RRM), Silicon", Forward Voltage=320mV, Manufacturer=Diodes, Max Operating Temperature=125°C, Max Output current=1A, Max Power Dissipation=450mW, Min Operating Temperature=-65°C, Non-rep Pk Forward Current-Max=25A, Package Body Material=Plastic, Package Shape=Rectangular, Package Style="SMALL OUTLINEMeter", Peak Reflow Temperature (Cel)=260°C, Rep Pk Reverse Voltage-Max=40V, Supplier Part Number=621-1N5819HW-F, Time @ Peak Reflow Temperature-Max (s)=40s
D4: "Rectifier Diode, Schottky, 1 Phase, 1 Element, 1A, 100V V(RRM), Silicon", Case Connection=CATHODE, Forward Voltage=770mV, Manufacturer=Diodes, Max Operating Temperature=175°C, Max Output current=1A, Min Operating Temperature=-55°C, Non-rep Pk Forward Current-Max=40A, Package Body Material=Plastic, Package Shape=Rectangular, Package Style="SMALL OUTLINEMeter", Peak Reflow Temperature (Cel)=260°C, Rep Pk Reverse Voltage-Max=100V, Supplier Part Number=DFLS1100DICT-ND, Time @ Peak Reflow Temperature-Max (s)=40s
D5: "Single Color LED, Amber, Water Clear, 1.1mm", Manufacturer="Wurth Electronics", Supplier Part Number=732-150060AS75000CT-ND
D6 D7: library part BZX84C12LT1G, "Zener Diode, 12V V(Z), 5.39%, 0.25W, Silicon, Unidirectional, TO-236AB", Manufacturer="ON Semiconductor", Max Operating Temperature=150°C, Max Power Dissipation=250mW, Min Operating Temperature=-65°C, Package Body Material=Plastic, Package Shape=Rectangular, Package Style="SMALL OUTLINEMeter", Peak Reflow Temperature (Cel)=260°C, Reference Voltage-Nom=12V, Supplier Part Number=863-BZX84C12LT1G, Test Current=5mA, Time @ Peak Reflow Temperature-Max (s)=40s, Voltage Tol-Max=5.39%
D8: library part BZX84B24VLFHT116, "Zener Diode, 24V V(Z), 2.08%, 0.25W, Silicon, Unidirectional"
D9: library part PESD2CANFD36LT-QR, "ESD Protection Diodes / TVS Diodes ESD protection for in-vehicle networks", Manufacturer=Nexperia, Supplier Part Number=771-PESD2CANFD36LTQR
F1: "Data Line Filter, 2 Function(s), 16V, 0.1A, 4 Pin(s)", Current Rating=100mA, DC Resistance-Max=2R, Insulation Resistance-Min=100MR, Manufacturer=Murata, Max Operating Temperature=85°C, Min Operating Temperature=-40°C, Supplier Part Number=81-DLP31SN121ML2L, Voltage Rating=16V
J1: "AMPHENOL SINE/TUCHEL - ATM13-12PA-12PB-BM03 - ATM HEADER  (2) 12 POSITION SIZE 20, A&B KEY  - TIN PLATING 98AC7190", Manufacturer_Name=Amphenol, Mouser Part Number=654-ATM1312A12PBBM03
L1: library part 744776112, "General Purpose Inductor, 12uH, 20%, 1 Element, Nickel-zinc Ferrite-Core, SMD, 3935", DC Resistance (DCR)=70mR, Inductor Application="POWER INDUCTOR", Inductor Type="GENERAL PURPOSE INDUCTOR", Manufacturer="Wurth Electronics", Max Current Rating=2.72A, Max Operating Temperature=125°C, Min Operating Temperature=-40°C, Self Resonant Frequency=20MHz, Supplier Part Number=710-744776112, Test Frequency=1kHz, Tolerance=20%
L2: library part SRR6838A-150M, "Power Inductors - SMD Ind,6.8x6.8x3.8mm,15uH+/-20%,2.1A,", Manufacturer=Bourns, Supplier Part Number=652-SRR6838A-150M
Q1 Q4: "Small Signal Bipolar Transistor, 0.6A I(C), 150V V(BR)CEO, 1-Element, PNP, Silicon, TO-236", Collector-emitter Voltage-Max=150V, DC Current Gain-Min (hFE)=50, Frequency=100MHz, Manufacturer=Diotec, Max Collector Current=600mA, Max Operating Temperature=150°C, Package Body Material=Plastic, Package Shape=Rectangular, Package Style="SMALL OUTLINEMeter", Peak Reflow Temperature (Cel)=260°C, Supplier Part Number=637-MMBT5401
Q2 Q3: library part IRF5210STRLPBF, "Zener Diode, 24V V(Z), 2.08%, 0.25W, Silicon, Unidirectional", Avalanche Energy Rating (Eas)=120mJ, Case Connection=DRAIN, Drain Current-Max (Abs) (ID)=38A, Drain-source On Resistance-Max=60mR, DS Breakdown Voltage-Min=100V, Manufacturer=Infineon, Max Operating Temperature=150°C, Operating Mode="ENHANCEMENT MODE", Package Body Material=Plastic, Package Shape=Rectangular, Package Style="SMALL OUTLINEMeter", Peak Reflow Temperature (Cel)=260°C, Power Dissipation-Max (Abs)=170W, Pulsed Drain Current-Max (IDM)=140A, Supplier Part Number=942-IRF5210STRLPBF, Time @ Peak Reflow Temperature-Max (s)=30s
R1: library part AC0402JR-7D0RL, "Fixed Resistor, Metal Glaze/thick Film, 0.0625W, 0ohm, Surface Mount, 0402", Manufacturer=Yageo, Supplier Part Number=603-AC0402JR-7D0RL
R2: library part AF0402FR-0743KL, "Fixed Resistor, Metal Glaze/thick Film, 0.0625W, 43000ohm, 50V, 1% +/-Tol, 100ppm/Cel, Surface Mount, 0402", Case/Package=0402, Manufacturer=Yageo, Max Operating Temperature=155°C, Min Operating Temperature=-55°C, Package Height=0.32mm, Package Length=1mm, Package Width=0.5mm, Power=62.5mW, Rated Temperature=70°C, Resistor Type="FIXED RESISTOR", Supplier Part Number=603-AF0402FR-0743KL, Temperature Coefficient (ppm/Cel)=100, Tolerance=1%, Working Voltage=50V
R3: library part AT0402DRD071K3L, "Fixed Resistor, Thin Film, 0.0625W, 1300ohm, 50V, 0.5% +/-Tol, 25ppm/Cel, Surface Mount, 0402", Case/Package=0402, Manufacturer=Yageo, Max Operating Temperature=155°C, Min Operating Temperature=-55°C, Package Height=0.3mm, Package Length=1mm, Package Shape=Rectangular, Package Width=0.5mm, Power=62.5mW, Rated Temperature=70°C, Resistor Type="FIXED RESISTOR", Supplier Part Number=603-AT0402DRD071K3L, Temperature Coefficient (ppm/Cel)=25, Tolerance=0.5%, Working Voltage=50V
R4: library part AC0402FR-072K7L, "Fixed Resistor, Metal Glaze/thick Film, 0.0625W, 2700ohm, 50V, 1% +/-Tol, 100ppm/Cel, Surface Mount, 0402", Case/Package=0402, Manufacturer=Yageo, Max Operating Temperature=155°C, Min Operating Temperature=-55°C, Package Height=0.32mm, Package Length=1mm, Package Shape=Rectangular, Package Width=0.5mm, Power=62.5mW, Rated Temperature=70°C, Resistor Type="FIXED RESISTOR", Supplier Part Number=603-AC0402FR-072K7L, Temperature Coefficient (ppm/Cel)=100, Tolerance=1%, Working Voltage=50V
R5: library part RT0402BRE0751K1L, "Fixed Resistor, Thin Film, 0.0625W, 51100ohm, 50V, 0.1% +/-Tol, 50ppm/Cel, Surface Mount, 0402", Case/Package=0402, Manufacturer=Yageo, Max Operating Temperature=155°C, Min Operating Temperature=-55°C, Package Height=0.3mm, Package Length=1mm, Package Width=0.5mm, Power=62.5mW, Rated Temperature=70°C, Resistor Type="FIXED RESISTOR", Supplier Part Number=603-RT0402BRE0751K1L, Temperature Coefficient (ppm/Cel)=50, Tolerance=0.1%, Working Voltage=50V
R6 R25: library part RC0402FR-1330KL, "Fixed Resistor, Metal Glaze/thick Film, 0.0625W, 30000ohm, 50V, 1% +/-Tol, 100ppm/Cel, Surface Mount, 0402", Case/Package=0402, Manufacturer=Yageo, Max Operating Temperature=155°C, Min Operating Temperature=-55°C, Package Height=0.35mm, Package Length=1mm, Package Shape=Rectangular, Package Width=0.5mm, Power=62.5mW, Rated Temperature=70°C, Resistor Type="FIXED RESISTOR", Supplier Part Number=603-RC0402FR-1330KL, Temperature Coefficient (ppm/Cel)=100, Tolerance=1%, Working Voltage=50V
R7: library part RC0402BR-078K2L, "Fixed Resistor, Metal Glaze/thick Film, 0.0625W, 8200ohm, 50V, 0.1% +/-Tol, 100ppm/Cel, Surface Mount, 0402", Manufacturer=Yageo, Supplier Part Number=603-RC0402BR-078K2L
R8 R19: library part RC0402FR-7W4K7L, "Fixed Resistor, Metal Glaze/thick Film, 0.125W, 4700ohm, 50V, 1% +/-Tol, 200ppm/Cel, Surface Mount, 0402", Case/Package=0402, Manufacturer=Yageo, Max Operating Temperature=155°C, Min Operating Temperature=-55°C, Package Height=0.35mm, Package Length=1mm, Package Shape=Rectangular, Package Width=0.5mm, Power=125mW, Rated Temperature=70°C, Resistor Type="FIXED RESISTOR", Supplier Part Number=603-RC0402FR-7W4K7L, Temperature Coefficient (ppm/Cel)=200, Tolerance=1%, Working Voltage=50V
R9 R28: library part RC0402FR-7D3K3L, "Fixed Resistor, Metal Glaze/thick Film, 0.0625W, 3300ohm, 50V, 1% +/-Tol, 100ppm/Cel, Surface Mount, 0402", Case/Package=0402, Manufacturer=Yageo, Max Operating Temperature=155°C, Min Operating Temperature=-55°C, Package Height=0.35mm, Package Length=1mm, Package Shape=Rectangular, Package Width=0.5mm, Power=62.5mW, Rated Temperature=70°C, Resistor Type="FIXED RESISTOR", Supplier Part Number=603-RC0402FR-7D3K3L, Temperature Coefficient (ppm/Cel)=100, Tolerance=1%, Working Voltage=50V
R10: library part AC0402FR-071K05L, "Fixed Resistor, Metal Glaze/thick Film, 0.0625W, 1050ohm, 50V, 1% +/-Tol, 100ppm/Cel, Surface Mount, 0402", Case/Package=0402, Manufacturer=Yageo, Max Operating Temperature=155°C, Min Operating Temperature=-55°C, Package Height=0.32mm, Package Length=1mm, Package Shape=Rectangular, Package Width=0.5mm, Power=62.5mW, Rated Temperature=70°C, Resistor Type="FIXED RESISTOR", Supplier Part Number=603-AC0402FR-071K05L, Temperature Coefficient (ppm/Cel)=100, Tolerance=1%, Working Voltage=50V
R11 R12 R13 R14 R15 R16 R17: library part AC0402JR-7W15KL, "Chip Resistor Automotive Grade Thick Film 0402 15kOhm 5% Paper T/R", Manufacturer=Yageo, Supplier Part Number=603-AC0402JR-7W15KL
R18 R29 R35: library part RT0402FRE101KL, "Fixed Resistor, Thin Film, 0.0625W, 1000ohm, 50V, 1% +/-Tol, 50ppm/Cel, Surface Mount, 0402", Manufacturer=Yageo, Supplier Part Number=603-RT0402FRE101KL
R20: library part CSS0402FT10L0, "Fixed Resistor, Metal Alloy, 0.33W, 0.01ohm, 1% +/-Tol, 100ppm/Cel, Surface Mount, 0402", Manufacturer="Stackpole Electronics", Supplier Part Number=708-CSS0402FT10L0
R21 R22: library part RP0402DRD07100RL, "Res, 100R, 0.5%, 0.063W, Thin Film, 0402 Rohs Compliant: Yes", Manufacturer=Yageo, Supplier Part Number=603-RP0402DRD07100RL
R23: library part AC0402FR-7D120RL, "Fixed Resistor, Metal Glaze/thick Film, 0.0625W, 120ohm, 50V, 1% +/-Tol, -100,100ppm/Cel, 0402", Case/Package=0402, Manufacturer=Yageo, Max Operating Temperature=155°C, Min Operating Temperature=-55°C, Package Height=0.32mm, Package Length=1mm, Package Width=0.5mm, Power=62.5mW, Resistor Type="FIXED RESISTOR", Supplier Part Number=603-AC0402FR-7D120RL, Temperature Coefficient (ppm/Cel)=-100,100, Tolerance=1%, Working Voltage=50V
R24 R27 R38 R39 R40 R42 R43: library part RP0402BRD0710KL, "Resistor, 10K, 0.1%, 0.063W, THIN FILM, 0402;", Manufacturer=Yageo, Supplier Part Number=603-RP0402BRD0710KL
R26: library part TNPW040217K2BEED, "Fixed Resistor, Thin Film, 0.063W, 17200ohm, 50V, 0.1% +/-Tol, 25ppm/Cel, Surface Mount, 0402", Case/Package=0402, Manufacturer="Vishay Dale", Manufacturer Series=TNPW, Max Operating Temperature=125°C, Min Operating Temperature=-55°C, Package Shape=Rectangular, Power=63mW, Rated Temperature=70°C, Resistor Type="FIXED RESISTOR", Supplier Part Number=71-TNPW040217K2BEED, Temperature Coefficient (ppm/Cel)=25, Tolerance=0.1%, Working Voltage=50V
R30 R41: library part RC0402FR-7D33KL, "Fixed Resistor, Metal Glaze/thick Film, 0.0625W, 33000ohm, 50V, 1% +/-Tol, 100ppm/Cel, Surface Mount, 0402", Manufacturer=Yageo, Supplier Part Number=603-RC0402FR-7D33KL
